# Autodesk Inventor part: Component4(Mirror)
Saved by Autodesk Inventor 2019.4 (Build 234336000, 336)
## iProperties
Created: 2020-06
Part Number: Component4(Mirror)
Material: Generic
Document SubType Name: Modeling
Designer: Administrator
Density: 1 g/cm^3
Appearance: Default
Title: Component4(Mirror)
Author: Administrator
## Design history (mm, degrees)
